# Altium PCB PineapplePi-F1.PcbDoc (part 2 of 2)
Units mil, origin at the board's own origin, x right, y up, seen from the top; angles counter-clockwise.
Board outline 1965 x 3150 mil, 2 copper layers (Top Layer, Bottom Layer); 93 components, 95 nets, 510 pads, 397 vias.
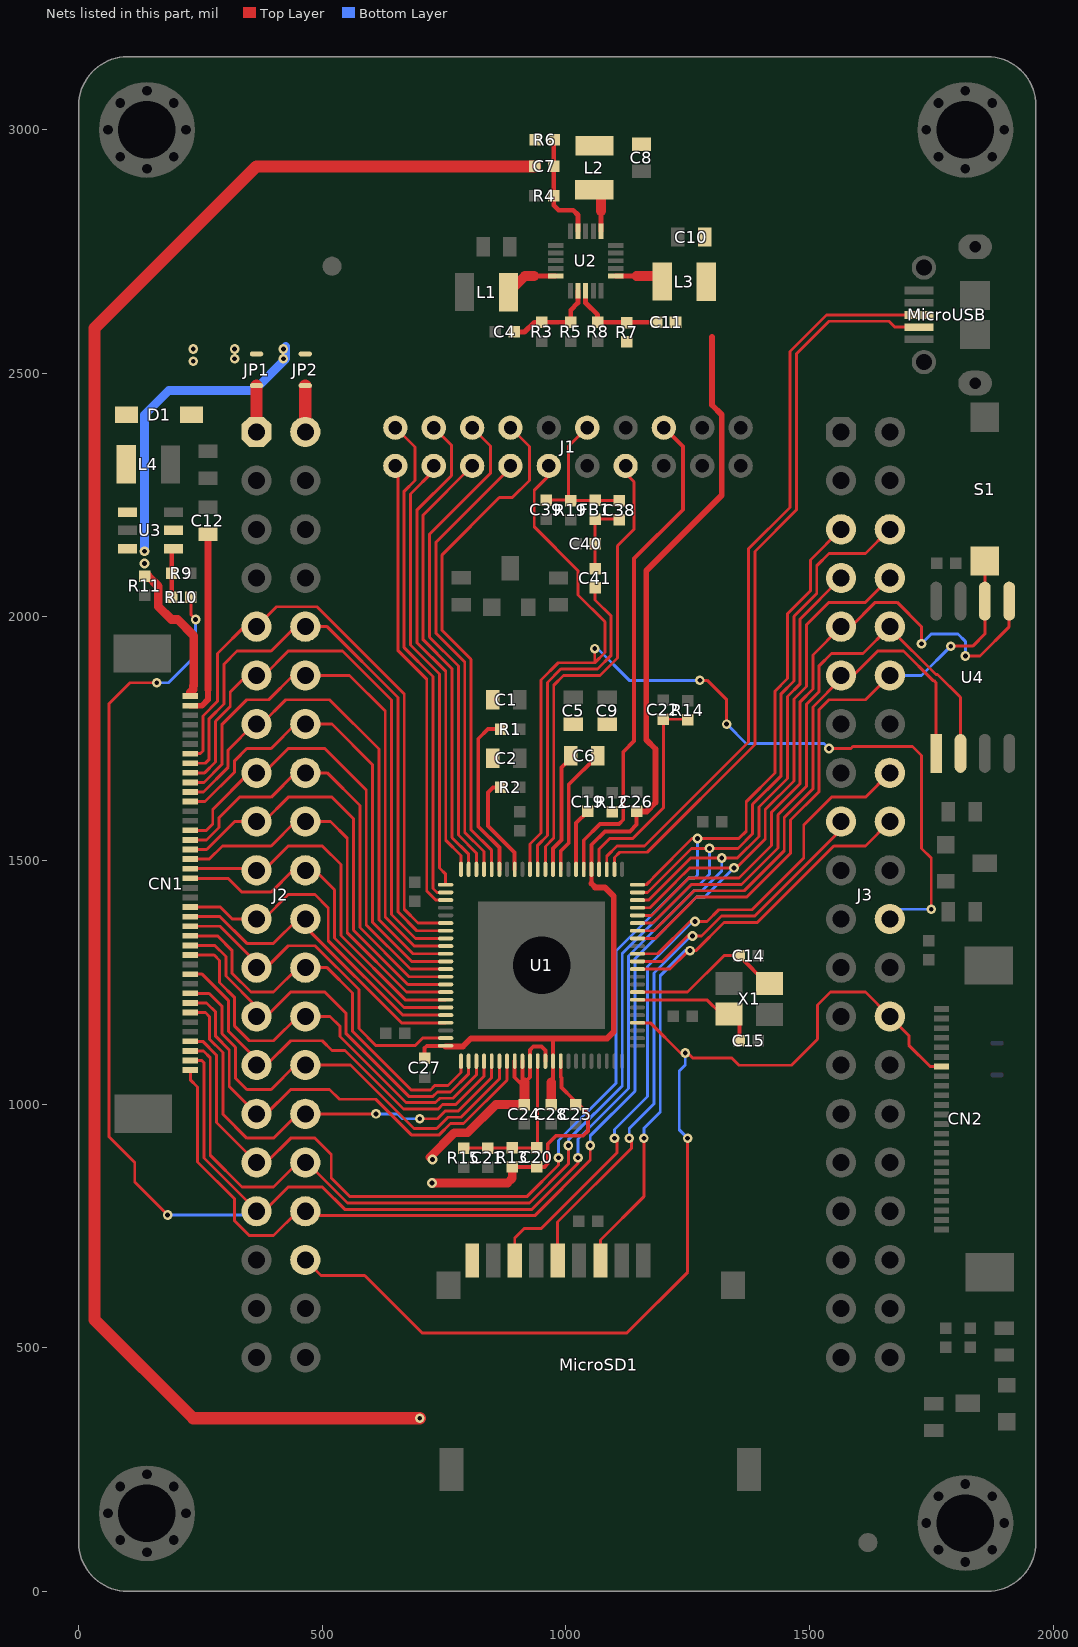
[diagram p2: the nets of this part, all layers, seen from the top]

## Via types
v1: diameter 20, hole 10, Top Layer to Bottom Layer, tented both sides, 286 vias
v2: diameter 20, hole 10, Top Layer to Bottom Layer, 109 vias
v3: diameter 39.37, hole 39.37, Top Layer to Bottom Layer, 2 vias

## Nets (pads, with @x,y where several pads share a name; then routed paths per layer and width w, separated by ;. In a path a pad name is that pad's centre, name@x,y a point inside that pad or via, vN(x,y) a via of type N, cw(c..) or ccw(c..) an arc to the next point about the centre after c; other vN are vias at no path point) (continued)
CSI_VSYNC: CN2.18 J2.36 J3.26 U1.48 | length 2199.8
  Top Layer w6: J2.36@465,680 497,648 587,648 705,530 1125,530 1250,655 v2(1250,930) ; U1.48@1146.85,1166.89 1173.11,1166.89 1235,1105 v2(1245,1105) 1250,1105 1260,1095 1340,1095 1355.3,1079.7 1463.09,1079.7 1516.62,1133.23 1516.62,1203.38 1543.23,1230 1615,1230 J3.26@1665,1180 1704,1141 1704,1121 1747.91,1077.09 CN2.18@1771,1077.09
  Bottom Layer w6: v2(1245,1105) 1245,1080 1232.69,1067.69 1232.69,947.31 v2(1250,930)
FM_INL: J1.8 U1.84 | length 1054.8
  Top Layer w6: U1.84@847.64,1481.85 847.64,1520.9 805.4,1563.14 805.4,1912.98 746,1972.38 746,2127.62 863.38,2245 890,2245 925,2280 925,2349.96 J1.8@886.22,2388.74
FM_INR: J1.7 U1.85 | length 932.6
  Top Layer w6: U1.85@831.89,1481.85 831.89,1518.26 792.4,1557.75 792.4,1907.6 733,1967 733,2153 886.22,2306.22 J1.7@886.22,2310
GPIO_PA0: CN1.37 J2.31 J3.5 U1.66 | length 2830.2
  Top Layer w6: CN1.37@229,1128.89 254.49,1128.89 283,1100.38 283,962 J2.31@365,880 385,880 435,930 485,930 518.38,896.62 518.38,848.38 556.77,810 919.85,810 985,875.15 v2(985,890) ; U1.66@1146.85,1450.35 1164.89,1450.35 1179.77,1465.23 1179.77,1465.63 1259.14,1545 v2(1270,1545) 1355,1545 1370.26,1560.26 1370.26,1620.72 1429,1679.46 1429,1847.69 1455,1873.69 1455,2006.77 1502,2053.77 1502,2117 J3.5@1565,2180
  Bottom Layer w6: v2(985,890) 985,925 1102.69,1042.69 1102.69,1314.52 1252.18,1464 1264,1464 1270,1470 v2(1270,1545)
GPIO_PA1: CN1.38 J2.32 J3.6 U1.65 | length 2947.2
  Top Layer w6: CN1.38@229,1109.21 255.79,1109.21 270,1095 270,895 335,830 400,830 450,880 J2.32@465,880 468.38,880 551.38,797 925.23,797 1005,876.77 v2(1005,915) ; U1.65@1146.85,1434.61 1167.53,1434.61 1193.96,1461.04 1193.96,1461.23 1257.73,1525 v2(1295,1525) 1353.38,1525 1383.26,1554.88 1383.26,1615.34 1442,1674.08 1442,1842.31 1468,1868.31 1468,2001.38 1515,2048.38 1515,2105 1540,2130 1615,2130 J3.6@1665,2180
  Bottom Layer w6: v2(1005,915) 1005,926.62 1115.69,1037.31 1115.69,1309.13 1257.56,1451 1274.23,1451 1295,1471.77 v2(1295,1525)
GPIO_PA2: CN1.39 J2.33 J3.7 R10.1 U1.64 | length 4407.9
  Top Layer w6: v2(160,1865) 105,1865 62.5,1822.5 62.5,932.5 115,880 115,840 v2(182.5,772.5) ; CN1.39@229,1089.52 252.48,1089.52 257,1085 257,889.62 365,781.62 J2.33@365,780 380,780 430,830 500,830 546,784 930.62,784 1025,878.38 v2(1025,890) ; R10.1@230,2040 230,2005 v2(240,1995) ; U1.64@1146.85,1418.86 1170.17,1418.86 1210.65,1459.35 1210.65,1459.54 1256.11,1505 v2(1320,1505) 1351.77,1505 1396.26,1549.49 1396.26,1609.95 1455,1668.69 1455,1836.92 1481,1862.92 1481,1996 J3.7@1565,2080
  Bottom Layer w6: v2(160,1865) 184.14,1865 240,1920.86 v2(240,1995) ; v2(182.5,772.5) 357.5,772.5 J2.33@365,780 ; v2(1025,890) 1025,928.23 1128.69,1031.92 1128.69,1303.75 1262.95,1438 1279.62,1438 1320,1478.38 v2(1320,1505)
GPIO_PA3: CN1.40 J2.34 J3.8 U1.63 | length 2912
  Top Layer w6: CN1.40@229,1069.84 229,1050 244,1035 244,881 320,805 320,760 350,730 400,730 450,780 J2.34@465,780 ; J2.34@476.77,780 J2.34@465,780 ; v2(1050,915) 1050,885 936,771 474,771 J2.34@465,780 ; U1.63@1146.85,1403.11 1172.8,1403.11 1226.27,1456.57 1226.27,1456.77 1254.5,1485 v2(1345,1485) 1350.15,1485 1409.26,1544.11 1409.26,1604.57 1468,1663.31 1468,1831.54 1494,1857.54 1494,1984 1540,2030 1615,2030 J3.8@1665,2080
  Bottom Layer w6: v2(1050,915) 1050,934.85 1141.69,1026.54 1141.69,1298.36 1268.33,1425 1285,1425 v2(1345,1485)
GPIO_PC0: J3.12 S1.1 U1.59 U4.6 | length 1260.6
  Top Layer w6: U1.59@1146.85,1340.12 1183.35,1340.12 1244.23,1401 1244.33,1401 1248,1404.67 1248,1404.77 1268.23,1425 1371.46,1425 1461.26,1514.8 1461.26,1583.03 1520,1641.77 1520,1810 1540,1830 1615,1830 J3.12@1665,1880 ; v2(1790,1940) 1835,1940 1860,1965 U4.6@1860,2032.6 S1.1@1860,2115
  Bottom Layer w6: J3.12@1665,1880 1730,1880 v2(1790,1940)
GPIO_PC1: J3.11 U1.60 U4.1 | length 1165.3
  Top Layer w6: U1.60@1146.85,1355.87 1180.71,1355.87 1262.85,1438 1366.08,1438 1448.26,1520.18 1448.26,1588.41 1507,1647.15 1507,1815.38 1565,1873.38 J3.11@1565,1880 1590,1880 1640,1930 1693.23,1930 1754.23,1869 1756,1869 1760,1865 U4.1@1760,1720
GPIO_PC2: J3.10 U1.61 U4.2 | length 1261.9
  Top Layer w6: U1.61@1146.85,1371.61 1178.08,1371.61 1257.46,1451 1360.69,1451 1435.26,1525.57 1435.26,1593.8 1494,1652.54 1494,1820.77 1520,1846.77 1520,1900 1545,1925 1610,1925 J3.10@1665,1980 1665,1976.62 1759.62,1882 1763,1882 1810,1835 U4.2@1810,1720
GPIO_PC3: J3.9 U1.62 U4.5 | length 1386.6
  Top Layer w6: U1.62@1146.85,1387.36 1175.44,1387.36 1241.65,1453.57 ; 1241.65,1453.77 1241.65,1453.57 ; v2(1730,1945) 1730,1980 1680,2030 1635,2030 1585,1980 J3.9@1565,1980 1507,1922 1507,1852.15 1481,1826.15 1481,1657.92 1422.26,1599.18 1422.26,1530.95 1355.31,1464 1252.08,1464 1241.65,1453.57 ; v2(1820,1920) 1850,1920 1910,1980 U4.5@1910,2032.6
  Bottom Layer w6: v2(1730,1945) 1750,1965 1805,1965 1820,1950 v2(1820,1920)
GPIO_PF1: J3.16 MicroSD1.7 U1.57 | length 1586.7
  Top Layer w6: MicroSD1.7@895,679 895,725 915,745 950,745 1105,900 1105,930 v2(1100,930) ; U1.57@1146.85,1308.62 1188.62,1308.62 1255,1375 v2(1265,1375) 1289.85,1375 1313.85,1399 1382.23,1399 1488.23,1505 1488.23,1573.23 1545,1630 1615,1630 J3.16@1665,1680
  Bottom Layer w6: v2(1100,930) 1100,948.08 1167.69,1015.77 1167.69,1282.69 v2@1260,1375
GPIO_PF2: J3.17 MicroSD1.5 U1.56 | length 1326.6
  Top Layer w6: MicroSD1.5@983,679 983,758 1135,910 1135,930 v2(1130,930) ; U1.56@1146.85,1292.87 1197.87,1292.87 v2@1250,1345 ; v2(1260,1345) 1278.23,1345 1319.23,1386 1387.62,1386 1565,1563.38 J3.17@1565,1580
  Bottom Layer w6: v2(1130,930) 1130,950 1180.69,1000.69 1180.69,1269.08 1256.62,1345 v2(1260,1345)
GPIO_PF3: J3.18 MicroSD1.3 U1.55 | length 1361.8
  Top Layer w6: MicroSD1.3@1071,679 1071,721 1160,810 v2(1160,930) ; U1.55@1146.85,1277.13 1213.9,1277.13 1248,1311.23 1248,1311.38 1251.62,1315 v2(1255,1315) 1266.62,1315 1324.62,1373 1393,1373 1550,1530 1615,1530 J3.18@1665,1580
  Bottom Layer w6: v2(1160,930) 1160,950 1193.69,983.69 1193.69,1263.69 1245,1315 v2(1255,1315)
HPCOM: J1.1 U1.3 | length 938.7
  Top Layer w6: J1.1@655,2305 655,1931.62 714.4,1872.21 714.4,1437.21 732.76,1418.86 U1.3@753.15,1418.86
HPCOMFB: J1.2 U1.2 | length 1025.5
  Top Layer w6: J1.2@650,2388.74 690,2348.74 690,2280 668,2258 668,1937 727.4,1877.6 727.4,1442.6 735.39,1434.61 U1.2@753.15,1434.61
HPL: J1.3 U1.1 | length 909.3
  Top Layer w6: J1.3@728.74,2310 728.74,2300.36 681,2252.62 681,1942.38 740.4,1882.98 740.4,1484.6 753.15,1471.85 U1.1@753.15,1450.35
HPR: J1.4 U1.88 | length 988.9
  Top Layer w6: J1.4@728.74,2388.74 765,2352.48 765,2290 694,2219 694,1947.77 753.4,1888.37 753.4,1541.6 784.65,1510.35 U1.88@784.65,1481.85
LCD_CLK: CN1.30 J2.27 U1.26 | length 861.7
  Top Layer w6: CN1.30@229,1266.69 253.31,1266.69 307,1213 307,1149.92 365,1091.92 J2.27@365,1080 385,1080 435,1130 500,1130 520,1110 546.46,1110 666.46,990 737.92,990 746.92,999 773.85,999 831.89,1057.04 U1.26@831.89,1088.15
LCD_D2: CN1.7 J2.9 U1.6 | length 1258.5
  Top Layer w6: CN1.7@229,1719.44 249.44,1719.44 254.75,1724.75 254.75,1796.52 285,1826.77 285,1925 J2.9@345,1985 ; J2.9@365,1980 406,2021 489,2021 668.19,1841.81 668.19,1400.05 696.62,1371.61 U1.6@753.15,1371.61
LCD_D3: CN1.8 J2.10 U1.7 | length 1254.5
  Top Layer w6: CN1.8@229,1699.76 259.76,1699.76 267.75,1707.75 267.75,1791.13 298,1821.38 298,1903 325,1930 395,1930 J2.10@460,1995 ; J2.10@465,1980 510,1980 655.19,1834.81 655.19,1394.66 693.99,1355.87 U1.7@753.15,1355.87
LCD_D4: CN1.9 J2.11 U1.8 | length 1197.5
  Top Layer w6: CN1.9@229,1680.07 258.46,1680.07 280.75,1702.36 280.75,1785.75 311,1816 311,1846 J2.11@360,1895 ; J2.11@365,1880 380,1880 430,1930 541.62,1930 642.19,1829.43 642.19,1389.28 691.35,1340.12 U1.8@753.15,1340.12
LCD_D5: CN1.10 J2.12 U1.9 | length 1135.9
  Top Layer w6: CN1.10@229,1660.39 257.16,1660.39 293.75,1696.98 293.75,1778.75 345,1830 390,1830 440,1880 J2.12@460,1880 ; J2.12@465,1880 556,1880 629.19,1806.81 629.19,1383.89 688.71,1324.37 U1.9@753.15,1324.37
LCD_D6: CN1.11 J2.13 U1.10 | length 1039.3
  Top Layer w6: CN1.11@229,1640.7 255.86,1640.7 306.75,1691.59 306.75,1726.75 J2.13@360,1780 ; J2.13@365,1780 375,1780 425,1830 515,1830 616.19,1728.81 616.19,1378.51 686.08,1308.62 U1.10@753.15,1308.62
LCD_D7: CN1.12 J2.14 U1.11 | length 990.1
  Top Layer w6: CN1.12@234,1621.02 259.4,1621.02 320,1681.62 320,1705 345,1730 395,1730 445,1780 J2.14@465,1780 520,1780 603.19,1696.81 603.19,1373.12 683.44,1292.87 U1.11@753.15,1292.87
LCD_D10: CN1.15 J2.15 U1.12 | length 961.2
  Top Layer w6: CN1.15@229,1561.96 261.96,1561.96 275,1575 275,1605 350,1680 J2.15@365,1680 380,1680 430,1730 505,1730 590.19,1644.81 590.19,1367.74 680.8,1277.13 U1.12@753.15,1277.13
LCD_D11: CN1.16 J2.16 U1.13 | length 913
  Top Layer w6: CN1.16@229,1542.28 262.28,1542.28 288,1568 288,1588 330,1630 395,1630 445,1680 J2.16@465,1680 510,1680 577.19,1612.81 577.19,1362.35 678.16,1261.38 U1.13@753.15,1261.38
LCD_D12: CN1.17 J2.17 U1.14 | length 861.9
  Top Layer w6: CN1.17@229,1522.59 262.59,1522.59 320,1580 J2.17@365,1580 380,1580 430,1630 520,1630 564.19,1585.81 564.19,1356.97 675.53,1245.63 U1.14@753.15,1245.63
LCD_D13: CN1.18 J2.18 U1.15 | length 814.9
  Top Layer w6: CN1.18@229,1502.91 267.91,1502.91 295,1530 395,1530 445,1580 J2.18@465,1580 517,1580 551.19,1545.81 551.19,1351.58 672.89,1229.88 U1.15@753.15,1229.88
LCD_D14: CN1.19 J2.19 U1.16 | length 757.8
  Top Layer w6: CN1.19@229,1483.22 J2.19@361.78,1483.22 ; J2.19@365,1480 380,1480 430,1530 500,1530 538.19,1491.81 538.19,1346.2 670.25,1214.13 U1.16@753.15,1214.13
LCD_D15: CN1.20 J2.20 U1.17 | length 729.2
  Top Layer w6: CN1.20@229,1463.54 306.46,1463.54 335,1435 395,1435 440,1480 J2.20@465,1480 485,1480 525.19,1439.81 525.19,1340.82 667.62,1198.39 U1.17@753.15,1198.39
LCD_D18: CN1.23 J2.21 U1.18 | length 696.9
  Top Layer w6: CN1.23@229,1404.48 290.52,1404.48 315,1380 J2.21@365,1380 380,1380 430,1430 485,1430 512.19,1402.81 512.19,1335.43 664.98,1182.64 U1.18@753.15,1182.64
LCD_D19: CN1.24 J2.22 U1.19 | length 697.7
  Top Layer w6: CN1.24@229,1384.8 290.2,1384.8 345,1330 400,1330 450,1380 J2.22@465,1380 485,1380 465.73,1360.73 474.27,1360.73 474.27,1354.97 662.34,1166.89 U1.19@753.15,1166.89
LCD_D20: CN1.25 J2.23 U1.21 | length 722.1
  Top Layer w6: CN1.25@229,1365.11 289.89,1365.11 365,1290 J2.23@365,1280 385,1280 430,1325 485,1325 575,1235 575,1155 610,1120 690,1120 705.39,1135.39 U1.21@753.15,1135.39
LCD_D21: CN1.26 J2.24 U1.23 | length 839.4
  Top Layer w6: CN1.26@229,1345.43 284.57,1345.43 315,1315 315,1268.38 353.38,1230 400,1230 450,1280 J2.24@465,1280 510,1280 562,1228 562,1149.62 682.62,1029 721.76,1029 730.76,1038 757.69,1038 784.65,1064.95 U1.23@784.65,1088.15
LCD_D22: CN1.27 J2.25 U1.24 | length 845.7
  Top Layer w6: CN1.27@229,1325.74 279.26,1325.74 302,1303 302,1263 365,1200 J2.25@365,1180 385,1180 435,1230 505,1230 549,1186 549,1144.23 677.23,1016 727.15,1016 736.15,1025 763.08,1025 800.39,1062.32 U1.24@800.39,1088.15
LCD_D23: CN1.28 J2.26 U1.25 | length 879.4
  Top Layer w6: CN1.28@229,1306.06 277.94,1306.06 289,1295 289,1249.38 320,1218.38 320,1160 350,1130 400,1130 450,1180 J2.26@465,1180 516,1180 536,1160 536,1138.85 671.85,1003 732.53,1003 741.53,1012 768.46,1012 816.14,1059.68 U1.25@816.14,1088.15
LCD_DE: CN1.34 J2.30 U1.27 | length 920.4
  Top Layer w6: CN1.34@229,1187.95 260.05,1187.95 268,1180 268,1133.77 296,1105.77 296,979 345,930 400,930 450,980 J2.30@465,980 v2(610,980) ; v2(700,970) 736.3,970 752.3,986 779.23,986 847.64,1054.41 U1.27@847.64,1088.15
  Bottom Layer w6: v2(610,980) 655,980 665,970 v2(700,970)
LCD_HSYNC: CN1.32 J2.28 U1.28 | length 939.5
  Top Layer w6: CN1.32@229,1227.32 267.68,1227.32 294,1201 294,1144.54 322,1116.54 322,1053 345,1030 395,1030 445,1080 J2.28@465,1080 558.08,1080 688.08,950 734.69,950 757.69,973 784.62,973 863.39,1051.77 U1.28@863.39,1088.15
LCD_VSYNC: CN1.33 J2.29 U1.29 | length 962.3
  Top Layer w6: CN1.33@229,1207.63 262.37,1207.63 281,1189 281,1139.15 309,1111.15 309,1036 J2.29@365,980 385,980 435,1030 515,1030 535,1010 609.69,1010 682.69,937 740.07,937 763.07,960 790,960 879.13,1049.13 U1.29@879.13,1088.15
LEDA: C12.1 CN1.2 D1.2 JP1.1 U3.5 | length 377.8
  Top Layer w12: CN1.2@229,1817.87 252.87,1817.87 265,1830 265,1850
  Top Layer w15: C12.1@260,2165 265.5,2159.5 265.5,1850.5
  other v2: 235,2525 320,2530 235,2550 320,2550
LEDK: CN1.1 JP2.1 R11.2 U3.3 | length 938.2
  Top Layer w18: R11.2@135,2084 142.25,2084 163.19,2063.06 163.19,2021.56 189.75,1995 202.63,1995 236,1961.63 236,1859.23 235,1858.23 235,1851 229,1845
  Bottom Layer w18: v2(135,2135) 135,2415 185,2465 360,2465 425,2530 v2@425,2555
  other v2: 135,2110 420,2530 420,2550
LINE_IN: J1.6 U1.86 | length 1014
  Top Layer w6: J1.6@807.48,2388.74 845,2351.22 845,2295 720,2170 720,1958.54 779.4,1899.14 779.4,1552.37 816.14,1515.63 U1.86@816.14,1481.85
LRADC: J1.9 J3.22 U1.79 | length 2240.2
  Top Layer w6: U1.79@926.38,1481.85 926.38,1534.16 949,1556.78 949,1870.77 984.23,1906 1059.23,1906 ; J1.9@964.96,2310 964.96,2289.96 935,2260 935,2185 1025,2095 1025,2045 1080,1990 1080,1926.77 1059.23,1906 ; v2(1059.23,1935) 1059.23,1906 ; v2(1275,1870) 1290,1870 1330,1830 v2(1330,1780) ; v2(1540,1730) 1585,1730 1589,1734 1711.38,1734 1730,1715.38 1730,1525 1750,1505 v2(1750,1400) ; J3.22@1665,1380 J3.22@1685,1380
  Bottom Layer w6: v2(1059.23,1935) 1065,1935 1130,1870 v2(1275,1870) ; v2(1330,1780) 1370,1740 1530,1740 v2(1540,1730) ; J3.22@1685,1400 v2(1750,1400)
MIC_IN: J1.5 U1.87 | length 911
  Top Layer w6: U1.87@800.39,1481.85 800.39,1512.99 766.4,1546.98 766.4,1893.75 707,1953.15 707,2209.52 J1.5@807.48,2310 J1.5@807.48,2307.48
NetC4_2: C4.2 R3.1 R5.1 U2.2 | length 195.4
  Top Layer w10: C4.2@894,2585 915,2585 935,2605 R3.1@950,2605 R5.1@1010,2605 1010,2630 1024.75,2644.75 U2.2@1024.75,2670
NetC7_2: C7.2 R4.1 R6.1 U2.14 | length 225.2
  Top Layer w10: R6.1@975,2979 C7.2@975,2925 R4.1@975,2865 975,2845 985,2835 1015,2835 1024.76,2825.24 U2.14@1024.76,2792
NetC11_2: C11.2 R7.2 R8.1 U2.3 | length 196.1
  Top Layer w10: U2.3@1040.5,2670 1040.5,2644.5 1065,2620 R8.1@1065,2605 C11.2@1186,2605
NetC14_2: C14.2 U1.52 X1.3 | length 326.5
  Top Layer w6: U1.52@1146.85,1229.88 1249.88,1229.88 1325,1305 C14.2@1356,1305
  Top Layer w8: C14.2@1356,1305 1356,1304 1412,1248 X1.3@1418,1248
NetC15_2: C15.2 U1.51 X1.1 | length 234.2
  Top Layer w6: U1.51@1146.85,1214.13 1289.13,1214.13 1318.27,1185 X1.1@1335,1185
  Top Layer w8: C15.2@1356,1130 X1.1@1356,1164
NetC38_1: C38.1 C40.1 C41.2 FB1.2 | length 151
  Top Layer w6: C41.2@1060,2099 C40.1@1060,2150 FB1.2@1060,2201 C38.1@1109,2201
NetD1_1: D1.1 L4.2 U3.1
NetJ2_1: J2.1 JP1.2 | length 95
  Top Layer w25: J2.1@365,2380 JP1.2@365,2475
NetJ2_2: J2.2 JP2.2 | length 95
  Top Layer w25: J2.2@465,2380 JP2.2@465,2475
NetL1_2: L1.2 U2.20 | length 110.5
  Top Layer w10: 935.21,2699.79 U2.20@979,2699.79
  Top Layer w20: L1.2@882.36,2666.37 915.78,2699.79 935.21,2699.79
NetL2_1: L2.1 U2.11 | length 71
  Top Layer w10: U2.11@1072,2792 1072,2833
  Top Layer w20: 1072,2833 L2.1@1072,2863
NetL3_2: L3.2 U2.6 | length 100.2
  Top Layer w10: U2.6@1102,2699.74 1145,2699.74
  Top Layer w12: L3.2@1186.53,2699.74 L3.2@1197.64,2688.63
  Top Layer w20: 1145,2699.74 L3.2@1186.53,2699.74
NetR9_2: R9.2 R10.2 U3.4 | length 96.7
  Top Layer w10: R10.2@191,2040 R9.2@191,2090 U3.4@191,2136.71
RST_N: C22.2 R14.1 U1.70 | length 440.6
  Top Layer w6: U1.70@1068.11,1481.85 1068.11,1523.11 1090,1545 1137.43,1545 1200,1607.57 C22.2@1200,1791 ; C22.2@1200,1790 R14.1@1249,1790
SD_DECTEC: MicroSD1.9
SVREF: C20.1 C21.2 R13.1 R15.2 U1.33 | length 343.2
  Top Layer w6: R15.2@785,910 R13.1@890,910 ; R13.1@880,910 C20.1@940,910 ; C20.1@942.13,910 U1.33@942.13,1088.15
TV_IN0: C41.1 U1.78 | length 698.2
  Top Layer w6: U1.78@942.13,1481.85 942.13,1531.52 962,1551.4 962,1865.38 989.62,1893 1064.62,1893 1093,1921.38 1093,2002 1060,2035 C41.1@1060,2060
TV_IN1: J1.13 U1.77 | length 954.8
  Top Layer w6: U1.77@957.87,1481.85 957.87,1528.89 975,1546.01 975,1860 995,1880 1070,1880 1106,1916 1106,2146 1140,2180 1140,2277.44 1122.44,2295 J1.13@1122.44,2310
TV_INPUT: C38.2 C39.1 FB1.1 J1.12 R19.2 | length 306.8
  Top Layer w6: C39.1@960,2240 R19.2@999,2240 ; J1.12@1043.7,2388.74 1005,2350 1005,2244 R19.2@1010,2239 C38.2@1110,2239
TV_OUT: J1.16 U1.72 | length 1030.2
  Top Layer w8: U1.72@1036.61,1481.85 1036.61,1541.61 1070,1575 1109.18,1575 1117.81,1583.63 1117.81,1722.81 1140,1745 1140,2120 1240,2220 1240,2349.92 J1.16@1201.18,2388.74
TV_VRN: C6.1 C9.1 U1.75 | length 264.5
  Top Layer w8: U1.75@989.37,1481.85 989.37,1519.37 1005.87,1535.87 1005.87,1655.87 C6.1@1065,1715
TV_VRP: C5.1 C6.2 U1.76 | length 244.1
  Top Layer w8: U1.76@973.62,1481.85 973.62,1524.84 990.87,1542.08 990.87,1690.87 1000,1700 C6.2@1000,1715
USB_DM: MicroUSB.2@1725,2595 U1.68 | length 1530.5
  Top Layer w6: U1.68@1099.61,1481.85 1099.61,1506.22 1110.38,1517 1167,1517 1388,1738 1388,2134.62 1473,2219.62 1473,2539.62 1540.38,2607 1663,2607 1675,2595 MicroUSB.2@1725,2595
USB_DP: MicroUSB.3@1725,2620 U1.69 | length 1548.2
  Top Layer w6: U1.69@1083.86,1481.85 1083.86,1508.86 1105,1530 1161.62,1530 1375,1743.38 1375,2140 1460,2225 1460,2545 1535,2620 MicroUSB.3@1725,2620
VCC_DRAM: C7.1 C8.1 C20.2 C24.2 C25.2 L2.2 R6.2 R13.2 U1.30 U1.31 U1.32 U1.34 U1.36 | length 4894.3
  Top Layer w8: R13.2@890,871 C20.2@940,871 956,871 962.81,877.81 962.81,917.81 980,935 1035,935 1045,945 1045,980 C25.2@1030,995 ; U1.30@894.88,1088.15 894.88,1055.12 910.63,1039.37 U1.31@910.63,1088.15 ; 915.63,1044.37 926.38,1055.12 U1.32@926.38,1088.15 926.38,1111.38 933,1118 950,1118 957.87,1110.13 U1.34@957.87,1088.15 ; U1.36@989.37,1088.15 989.37,1055.33 991,1053.7 991,1034 C25.2@1015,1010
  Top Layer w18: v2@721.07,891.13 770.94,941 797.87,941 855.87,999 C24.2@915,999 ; v2(725,838) 880,838 890,848 R13.2@890,871
  Top Layer w20: C24.2@915,999 915,1045 915.63,1044.37
  Top Layer w25: v2(700,355) 235,355 32.5,557.5 32.5,2592.5 365,2925 C7.1@936,2925
  other v2: 726.07,886.13
VCC_TV: C19.2 R12.1 U1.73 | length 129.1
  Top Layer w8: U1.73@1020.87,1481.85 1020.87,1576.87 C19.2@1045,1601
VDD_CORE: C10.2 C11.1 C26.2 C27.2 C28.2 L3.1 R7.1 U1.22 U1.35 U1.71 | length 2210.8
  Top Layer w8: C27.2@710,1094 710,1115 714.65,1119.65 U1.22@753.15,1119.65 ; 970,1030 973.62,1033.62 U1.35@973.62,1088.15 973.62,1135 ; 1052.36,1452.64 U1.71@1052.36,1481.85 1052.36,1532.36 1080,1560 1131.21,1560 1145,1573.79 C26.2@1145,1601
  Top Layer w12: U1.22@753.15,1118.46 788.46,1118.46 805,1135 1085,1135 1098.35,1148.35 1098.35,1426.65 1080,1445 1060,1445 1052.36,1452.64 ; C26.2@1145,1601 1166,1601 1184,1619 1184,1729 1165,1748 1165,2095 1320,2250 1320,2415 1300,2435 1300,2575
  Top Layer w20: C28.2@970,999 970,1030 970,1045
VRA1: C2.1 R2.2 U1.81 | length 211
  Top Layer w8: R2.2@866,1650 850,1650 840,1640 840,1571.21 894.88,1516.33 U1.81@894.88,1481.85
VRA2: C1.1 R1.2 U1.83 | length 340.4
  Top Layer w8: U1.83@863.39,1481.85 863.39,1526.61 820,1570 820,1750 840,1770 R1.2@866,1770
pads on no net: CN1.35 CN2.1 CN2.2 CN2.24 MicroUSB.0@1735,2523.31 MicroUSB.1@1735,2717.28 MicroUSB.2@1840,2480 MicroUSB.3@1840,2760 MicroUSB.4 MP1.0 MP2.0
copper on no net:
  other v3: 876,234 1191,234

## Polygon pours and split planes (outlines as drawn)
AGND on Top Layer "Top Layer-No Net" (solid, remove dead copper, pour order 1000): 0,3150 5,3155 1970,3155 1970,0 0,0
AGND on Bottom Layer "Top Layer-No Net" (solid, remove dead copper, pour order 1001): 0,3150 1965,3150 1965,0 0,0

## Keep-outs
Keep-Out Layer:
  the board outline again, w20

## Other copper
Top Layer:
  rectangle net AGND: 1030,1825 1075,1845.12
  rectangle net AGND: 1135,1630 1155,1705
  rectangle net AGND: 1385,1115 1450,1205
  rectangle net AGND: 855,1585 905,1625
  rectangle net AGND: 680,1435 700,1470
  rectangle net LEDK: 405,2520 490,2565
  rectangle net LEDA: 310,2520 355,2565
  rectangle net LEDA: 215,2415 250,2565
  rectangle net +5V: 70,800 100,875
  rectangle net +5V: 70,2465 105,2545
  rectangle net CSI_IOVDD: 1010,455 1040,505
  rectangle net CSI_IOVDD: 1010,550 1040,600
  rectangle net AGND: 955,950 1030,975
  rectangle net AGND: 1305,1565 1355,1595
  rectangle net LEDK: 220,1835 245,1851
  rectangle net +5V: 1085,2760 1130,2820
  rectangle net +5V: 920.35,2762.78 990,2820
  rectangle net AGND: 230,2210 290,2305
  rectangle net +5V: 205,2320 285,2360
  rectangle net LEDA: 145,2160 170,2190
  rectangle net LEDA: 130,2160 160,2390
  rectangle net LEDA: 130,2390 255,2435
  rectangle net NetD1_1: 75,2205 120,2410
  rectangle net LEDK: 80,2070 150,2150
  rectangle net LEDA: 170,2160 285,2190
  rectangle net +5V: 170,2205 220,2360
  rectangle net +5V: 1130,2742.5 1157.5,2820
  rectangle net +5V: 1130,2734.07 1144.07,2820
  rectangle net VDD_CORE: 1210,2550 1310,2590
  rectangle net VDD_CORE: 1110,2550 1310,2580
  rectangle net VDD_CORE: 1210,2590 1260,2625
  rectangle net VDD_CORE: 1260,2590 1310,2805
  rectangle net CSI_IOVDD: 840,2570 870,2600
  rectangle net CSI_IOVDD: 770,2570 845,2780
  rectangle net AGND: 1005,2696 1076,2767
  rectangle net VCC_DRAM: 1015,2945 1175,3010
  rectangle net VCC_DRAM: 940,3000 1175,3025
  rectangle net VCC_DRAM: 925,2915 950,3025
  rectangle net VCC_DRAM: 1090,2955 1175,2985
  rectangle net VDD_CORE: 710,1085 755,1119.65
  rectangle net VRA2: 830,1755 880,1850
  rectangle net VRA1: 835,1635 880,1730
  rectangle net AVCC: 905,2000 1005,2040
  rectangle net CSI_IOVDD: 765,2065 905,2125
  rectangle net VCC_TV: 1040,1590 1105,1610
  rectangle net TV_VRP: 1000,1695 1025,1775
  rectangle net TV_VRN: 1055,1715 1075,1795
  rectangle net CSI_IOVDD: 1115,1475 1175,1495
  rectangle net CSI_IOVDD: 770,2535 965,2555
  rectangle net CSI_IOVDD: 780,2545 870,2570
  rectangle net CSI_IOVDD: 295,2000 325,2055
  rectangle net CSI_IOVDD: 200,1915 220,1955
  rectangle net CSI_IOVDD: 680,1480 700,1525
  rectangle net CSI_IOVDD: 510,2025 640,2125
  rectangle net AGND: 170,1265 200,1760
  rectangle net AGND: 170,1105 200,1230
  rectangle net AGND: 655,1075 685,1100
  rectangle net AGND: 670,1065 685,1075
  rectangle net CSI_IOVDD: 1325,2445 1355,2495
  rectangle net CSI_DVDD: 1880,405 1925,500
  rectangle net CSI_IOVDD: 1735,365 1850,410
  region net AGND: 1030,2135 1000,2135 945,2190 945,2215 1030,2215
  region net CSI_IOVDD: 511.59,2021.31 cw(c515.12,2024.88) 511.56,2021.35 686.45,1846.45 ccw(c690,1850) 695.01,1850 ccw(c690,1850) 693.55,1853.55 640,1900 640,2025 636.89,2026.08 ccw(c631.87,2026.08) 630.76,2030.97 517.2,2029.89 506.55,2040.55 ccw(c503,2037)
Bottom Layer:
  rectangle net LEDK: 405,2515 435,2565
  rectangle net LEDK: 120,2095 150,2150
  rectangle net LEDA: 215,2515 340,2565
  rectangle net +5V: 70,800 100,875
  rectangle net +5V: 70,2465 105,2545
  rectangle net VCC_DRAM: 660,320 740,900
  rectangle net CSI_IOVDD: 1010,455 1040,600
  rectangle net +5V: 925,2775 1155,2820
  rectangle net CSI_IOVDD: 295,2000 325,2055
  rectangle net CSI_IOVDD: 200,1915 220,1955
  rectangle net CSI_IOVDD: 200,2015 305,2055
  rectangle net CSI_IOVDD: 200,1945 220,2025
  rectangle net CSI_IOVDD: 680,1480 700,1525
  rectangle net CSI_IOVDD: 575,2070 635,2125
  rectangle net CSI_IOVDD: 805,2070 860,2125
  rectangle net CSI_IOVDD: 575,2070 860,2125
  rectangle net CSI_IOVDD: 1325,2445 1355,2495
  rectangle net CSI_AVDD: 1840,1130 1910,1145
  rectangle net CSI_DVDD: 1850,1040 1910,1055

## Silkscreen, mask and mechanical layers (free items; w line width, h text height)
Top Overlay:
  circle w10: c945,2675 r7.07
  lines w10: 255,730 315,730 ; 257.89,605 315,605 ; 260,930 315,930 ; 270,2030 315,2030 ; 280,1140 280,1145 290,1155 ; 280,1740 290,1730 ; 290,930 290,1155 ; 290,2030 290,1730 ; 300,1740 290,1730 ; 305,1140 290,1155
  text "3V3" at 1720,2400 h50
  text "+5V" at 1505,2345 h50 r90
  text "GND" at 1761,2245 h50 r90
  text "GND" at 1505,2235 h50 r90
  text "+5V" at 560,2220 h50 r90
  text "3V3" at 605,2215 h50 r90
  text "GNDx2" at 525,2170 h50
  text "A0|A1" at 1375,2165 h50
  text "GNDx2" at 525,2065 h50
  text "A2|A3" at 1375,2065 h50
  text "D0|D1" at 530,1970 h50
  text "C3|C2" at 1375,1965 h50
  text "1" at 250,1875 h50 r90
  text "D2|D3" at 530,1865 h50
  text "C1|C0" at 1375,1860 h50
  text "D4|D5" at 530,1765 h50
  text "GNDx2" at 1360,1765 h50
  text "D6|D7" at 525,1665 h50
  text "F0|F1" at 1380,1660 h50
  text "D8|D9" at 525,1565 h50
  text "F2|F3" at 1380,1565 h50
  text "D10|D11" at 525,1485 h50
  text "F4|F5" at 1380,1465 h50
  text "GND|ADC_KEY" at 1190,1370 h50
  text "D12|D13" at 530,1340 h50
  text "E0" at 1460,1290 h50 r90
  text "LCD-RGB 666" at 300,1280 h50 r90
  text "D14|D15" at 525,1260 h50
  text "GND" at 1505,1260 h50 r90
  text "24" at 1725,1255 h50 r270
  text "D16" at 525,1210 h50 r270
  text "D17" at 565,1210 h50 r270
  text "E2" at 1485,1200 h50 r90
  text "E1" at 1505,1150 h50 r90
  text "D18" at 525,1110 h50 r270
  text "D20" at 565,1110 h50 r270
  text "E4" at 1475,1085 h50 r90
  text "E3" at 1505,1035 h50 r90
  text "D21" at 525,1020 h50 r270
  text "D19" at 565,1020 h50 r270
  text "40" at 250,975 h50 r90
  text "E6|E5" at 1385,965 h50
  text "A0|A1" at 525,865 h50
  text "E8|E7" at 1385,865 h50
  text "SI" at 295,855 h50 r90
  text "CS" at 245,845 h50 r90
  text "SPI1" at 190,785 h50 r90
  text "A2|A3" at 525,770 h50
  text "E10|E9" at 1360,765 h50
  text "1" at 1718.76,760 h50 r270
  text "SO" at 295,755 h50 r90
  text "CLK" at 245,745 h50 r90
  text "E0|E1" at 525,670 h50
  text "E12|E11" at 1345,665 h50
  text "SCK" at 250,625 h50 r90
  text "SDA" at 300,625 h50 r90
  text "TWI2" at 190,615 h50 r90
  text "3V3" at 530,570 h50
  text "GND" at 205,565 h50
  text "GNDx2" at 1350,560 h50
  text "+5V" at 1755,475 h50 r90
  text "3V3" at 1420,465 h50
  text "GND" at 210,460 h50
  text "+5V" at 530,460 h50
  text "BoloPi-F1_V2" at 350,35 h80
Bottom Solder:
  rectangle: 1005,2696 1076,2767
